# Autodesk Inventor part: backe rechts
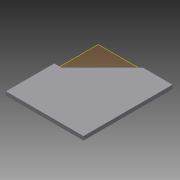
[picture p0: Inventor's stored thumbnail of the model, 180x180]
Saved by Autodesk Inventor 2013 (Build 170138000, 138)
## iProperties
Created: 2012-11
Part Number: backe rechts
Material: Allgemein
Document SubType Name: Modeling
Designer: otto
Density: 1 g/cm^3
d0: 10,000 mm
d1: 10,000 mm
d2: 10,000 mm
d3: 10,000 mm
d4: 60,000 mm
d5: 1,500 mm
d6: 0,00 grd
d7: 15,000 mm
d8: 0,00 grd
Author: otto
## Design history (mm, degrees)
sketch "Skizze2"
  geometry: L1 (62.842, 56.837)-(-16.083, -22.088) reference; L2 (62.842, 122.085)-(62.842, 56.837) reference; L3 (-3.226, -37.408)-(62.842, 28.66) reference; L4 (62.842, 28.66)-(62.842, -13.09) reference; L5 (62.842, -13.09)-(15.644, -60.289) reference; L6 (29.786, -74.431)-(62.842, -41.374) reference; L7 (62.842, -41.374)-(62.842, -94.979) reference; L8 (-14.414, -124.654)-(5.433, -104.806) reference; L9 (31.938, -124.654)-(-14.414, -124.654) reference; L10 (-7.843, -89.829)-(-42.668, -124.654) reference; L11 (-42.668, -124.654)-(-87.677, -124.654) reference; L12 (-87.677, -123.652)-(-29.098, -65.073) reference; L13 (103.52, -137.92)-(-134.48, -137.92) reference; L14 (103.52, -137.92)-(103.52, 384.83) reference; L15 (-134.48, 384.83)-(103.52, 384.83) reference; L16 (-134.48, -137.92)-(-134.48, 384.83) reference; L17 (-44.725, -52.895)-(-87.677, -95.847) reference; L18 (-87.677, -124.654)-(-87.677, -123.652) reference; L19 (-87.677, -95.847)-(-87.677, -45.538) reference; L20 (-125.48, -53.223)-(-125.48, 16.777) reference; L21 (-130.48, 16.777)-(-130.48, -53.223) reference; L22 (-130.48, -53.223)-(-125.48, -53.223) reference; L23 (99.52, 106.777)-(99.52, 176.777) reference; L24 (94.52, 176.777)-(94.52, 106.777) reference; L25 (94.52, 106.777)-(99.52, 106.777) reference; L26 (94.52, 176.777)-(99.52, 176.777); L27 (-130.48, 16.777)-(-125.48, 16.777); L28 (-135.48, 16.777)-(-130.48, 16.777) reference; L29 (99.52, 176.777)-(104.52, 176.777) reference; L30 (-135.48, 16.777)-(-135.48, 26.777); L31 (-135.48, 26.777)-(-125.48, 26.777); L32 (104.52, 176.777)-(104.52, 186.777); L33 (104.52, 186.777)-(94.52, 186.777); L34 (94.52, 186.777)-(34.52, 186.777); L35 (34.52, 186.777)-(-125.48, 26.777); 2 further points
  constraints: 16 end point, 4 perpendicular, 2 parallel, 1 collinear
  dimensions: "d0" = 10 distance of L28.start L30.end; "d1" = 10 distance of L30.end L31.end; "d2" = 10 distance of L29.end L32.end; "d3" = 10 distance of L32.end L33.end; "d4" = 60 distance of L33.end L34.end
extrude "Extrusion1" new body sketch "Skizze2" distance "d5" = 1.5; taper "d6" = 0 deg
workplane "Arbeitsebene1"
sketch "Skizze3"
  geometry: L1 (34.52, 186.777)-(-125.48, 26.777) reference; L2 (104.52, 186.777)-(34.52, 186.777) reference; L3 (104.52, 176.777)-(104.52, 186.777) reference; L4 (104.52, 176.777)-(104.52, 59.1) reference; L5 (104.52, 16.777)-(104.52, -143.223) reference; L6 (104.52, -143.223)-(-135.48, -143.223) reference; L7 (-135.48, -143.223)-(-135.48, 16.777) reference; L8 (-135.48, 26.777)-(-135.48, 16.777) reference; L9 (-125.48, 26.777)-(-135.48, 26.777) reference; A1 r 10.381 centre (114.837, 60.254) between (104.52, 59.1) and (115.363, 49.886) reference; A2 r 14.76 centre (116.112, 35.145) between (129.525, 28.983) and (115.363, 49.886) reference; A3 r 4.23 centre (125.681, 30.748) between (121.507, 31.429) and (129.525, 28.983) reference; A4 r 5.422 centre (116.156, 32.301) between (121.507, 31.429) and (112.095, 35.893) reference; A5 r 30.238 centre (134.744, 15.859) between (112.095, 35.893) and (104.52, 16.777) reference; 1 further point
extrude "Extrusion2" join sketch "Skizze3" distance "d7" = 15; taper "d8" = 0 deg
sketch "Skizze4"
  geometry: L1 (-135.48, 26.777)-(-135.48, -143.223) reference; L2 (-135.48, -143.223)-(104.52, -143.223) reference; L3 (104.52, -143.223)-(104.52, 16.777) reference; L4 (104.52, 59.1)-(104.52, 186.777) reference; L5 (104.52, 186.777)-(34.52, 186.777) reference; L6 (-155.48, -163.223)-(149.52, -163.223); L7 (149.52, -163.223)-(149.52, 186.777); L8 (104.52, 186.777)-(149.52, 186.777); L9 (-135.48, 26.777)-(-155.48, 26.777); L10 (-155.48, 26.777)-(-155.48, -163.223); A1 r 30.238 centre (134.744, 15.859) between (112.095, 35.893) and (104.52, 16.777) reference; A2 r 5.422 centre (116.156, 32.301) between (121.507, 31.429) and (112.095, 35.893) reference; A3 r 4.23 centre (125.681, 30.748) between (121.507, 31.429) and (129.525, 28.983) reference; A4 r 14.76 centre (116.112, 35.145) between (129.525, 28.983) and (115.363, 49.886) reference; A5 r 10.381 centre (114.837, 60.254) between (104.52, 59.1) and (115.363, 49.886) reference; 1 further point
  constraints: 10 end point, 3 perpendicular, 2 parallel
  dimensions: "d9" = 20 distance between parallel lines of L1 L10; "d10" = 45 distance between parallel lines of L7 L3; "d11" = 20 distance between parallel lines of L6 L2
extrude "Extrusion3" join sketch "Skizze4" distance "d12" = 15; taper "d13" = 0 deg
sketch "Skizze5"
  geometry: L1 (-94.52, 176.777)-(-104.52, 176.777) reference; L2 (-104.52, 186.777)-(-149.52, 186.777) reference; L3 (-149.52, 186.777)-(-149.52, -163.223) reference; L4 (-149.52, -163.223)-(155.48, -163.223) reference; L5 (155.48, -163.223)-(155.48, 26.777) reference; L6 (155.48, 26.777)-(135.48, 26.777) reference; L7 (130.48, 16.777)-(130.48, -53.223) reference; L8 (130.48, -53.223)-(125.48, -53.223) reference; L9 (125.48, -53.223)-(125.48, 16.777) reference; L10 (135.48, -143.223)-(135.48, 16.777) reference; L11 (-104.52, -143.223)-(135.48, -143.223) reference; L12 (-104.52, 16.777)-(-104.52, -143.223) reference; L13 (-104.52, 176.777)-(-104.52, 59.1) reference; L14 (-99.52, 176.777)-(-104.52, 176.777) reference; L15 (-104.52, 176.777)-(-94.52, 176.777) reference; L16 (135.48, 16.777)-(130.48, 16.777) reference; L17 (-34.52, 186.777)-(-104.52, 186.777) reference; L18 (125.48, 26.777)-(-34.52, 186.777) reference; L19 (135.48, 26.777)-(125.48, 26.777) reference; L20 (135.48, 16.777)-(130.48, 16.777) reference; L21 (125.48, 16.777)-(130.48, 16.777); A1 r 30.238 centre (-134.744, 15.859) between (-104.52, 16.777) and (-112.095, 35.893) reference; A2 r 5.422 centre (-116.156, 32.301) between (-112.095, 35.893) and (-121.507, 31.429) reference; A3 r 4.23 centre (-125.681, 30.748) between (-129.525, 28.983) and (-121.507, 31.429) reference; A4 r 14.76 centre (-116.112, 35.145) between (-115.363, 49.886) and (-129.525, 28.983) reference; A5 r 10.381 centre (-114.837, 60.254) between (-115.363, 49.886) and (-104.52, 59.1) reference; 1 further point
  constraints: 2 end point, 1 collinear
extrude "Extrusion4" join sketch "Skizze5" distance "d14" = 35.5; taper "d15" = 0 deg
node "Volumenkörper1"
node "Referenz41"
node "Referenz42"
node "Referenz43"
node "Referenz44"
node "Referenz45"
node "Referenz46"
node "Referenz47"
node "Referenz48"
node "Referenz49"
node "Referenz50"
node "Referenz51"
node "Referenz52"
node "Referenz53"
node "Referenz54"
node "Referenz55"
node "Referenz56"
node "Referenz57"
node "Referenz58"
node "Referenz59"
node "Referenz60"
node "Referenz61"
node "Referenz62"
node "Referenz63"
node "Referenz64"
node "Referenz65"
node "Referenz66"
node "Referenz67"
node "Referenz68"
node "Referenz69"
node "Referenz70"
node "Referenz71"
node "Referenz72"
node "Referenz73"
node "Referenz74"
node "Referenz75"
node "Referenz76"
node "Referenz77"
node "Referenz78"
node "Referenz79"
node "Referenz80"
node "Referenz81"
node "Referenz82"
node "Referenz83"
node "Referenz84"
node "Referenz85"
node "Referenz86"
node "Referenz87"
node "Referenz88"
node "Referenz89"
node "Referenz90"
node "Referenz91"
node "Referenz92"
node "Referenz93"
node "Referenz94"
node "Referenz95"
node "Referenz96"
